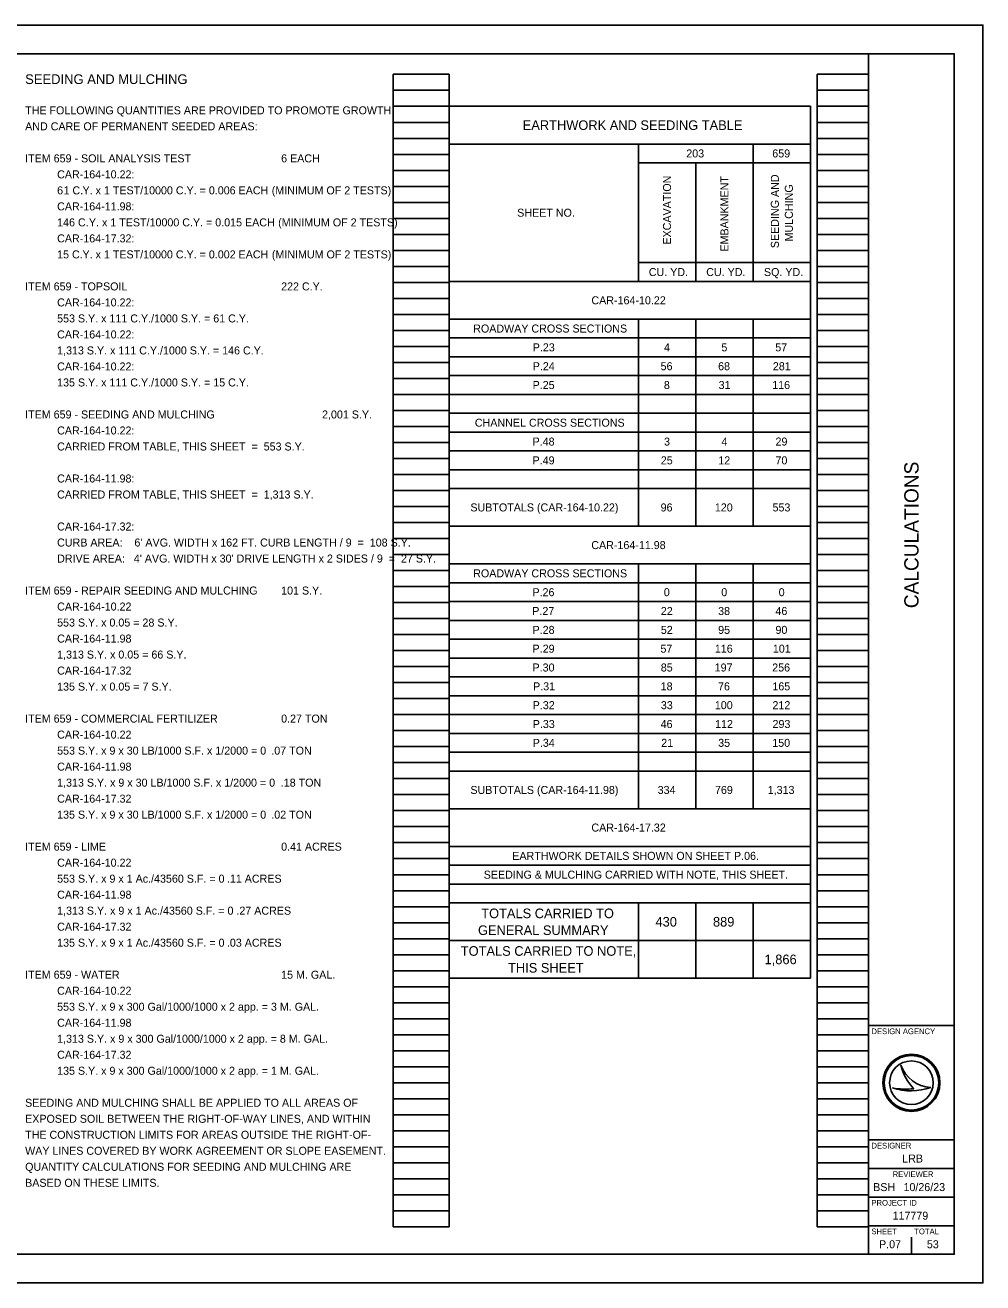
# Model space of a CAD drawing. Extents: x 0 to 34, y 0 to 22.
# Drawn here: x 17.24 to 34, y 0 to 22 of the extents above; entities that cross this region are included whole.
import ezdxf

# ---------------------------------------------------------------- set-up
doc = ezdxf.new("R2010")
doc.units = 0
for name, color, linetype in [('SH_Border', 7, 'Continuous'), ('SH_Cut_Line', 7, 'Continuous'), ('SH_Data', 7, 'Continuous'), ('SH_Text', 7, 'Continuous'), ('SV_X_Text', 7, 'Continuous')]:
    doc.layers.add(name, color=color, linetype=linetype)

msp = doc.modelspace()

# ---------------------------------------------------------------- linework, layer by layer
at = {"layer": 'SH_Border'}
for p, q in [((32, 0.5), (32, 21.5)), ((32, 4.5), (33.5, 4.5)), ((32, 2.5), (33.5, 2.5)), ((32, 2), (33.5, 2)), ((32, 1.5), (33.5, 1.5)), ((32, 1), (33.5, 1))]:
    msp.add_line(p, q, dxfattribs=at)
msp.add_lwpolyline([(1.5, 21.5), (33.5, 21.5), (33.5, 0.5), (1.5, 0.5)], close=True, dxfattribs=at)
at = {"layer": 'SH_Cut_Line'}
msp.add_lwpolyline([(0, 0), (34, 0), (34, 22), (0, 22)], close=True, dxfattribs=at)
at = {"layer": 'SH_Data'}
for p, q in [((23.68, 0.98), (23.68, 21.14)), ((23.68, 21.14), (24.66, 21.14)), ((24.66, 0.98), (24.66, 21.14)), ((31.1, 0.98), (31.1, 21.14)), ((31.1, 21.14), (32, 21.14)), ((32, 0.98), (32, 21.14)), ((23.68, 20.86), (24.66, 20.86)), ((31.1, 20.86), (32, 20.86)), ((23.68, 20.58), (24.66, 20.58)), ((31.1, 20.58), (32, 20.58)), ((23.68, 20.3), (24.66, 20.3)), ((31.1, 20.3), (32, 20.3)), ((23.68, 20.02), (24.66, 20.02)), ((31.1, 20.02), (32, 20.02)), ((23.68, 19.74), (24.66, 19.74)), ((31.1, 19.74), (32, 19.74)), ((23.68, 19.46), (24.66, 19.46)), ((31.1, 19.46), (32, 19.46)), ((23.68, 19.18), (24.66, 19.18)), ((31.1, 19.18), (32, 19.18)), ((23.68, 18.9), (24.66, 18.9)), ((31.1, 18.9), (32, 18.9)), ((23.68, 18.62), (24.66, 18.62)), ((31.1, 18.62), (32, 18.62)), ((23.68, 18.34), (24.66, 18.34)), ((31.1, 18.34), (32, 18.34)), ((23.68, 18.06), (24.66, 18.06)), ((31.1, 18.06), (32, 18.06)), ((23.68, 17.78), (24.66, 17.78)), ((31.1, 17.78), (32, 17.78)), ((23.68, 17.5), (24.66, 17.5)), ((31.1, 17.5), (32, 17.5)), ((23.68, 17.22), (24.66, 17.22)), ((31.1, 17.22), (32, 17.22)), ((23.68, 16.94), (24.66, 16.94)), ((31.1, 16.94), (32, 16.94)), ((23.68, 16.66), (24.66, 16.66)), ((31.1, 16.66), (32, 16.66)), ((23.68, 16.38), (24.66, 16.38)), ((31.1, 16.38), (32, 16.38)), ((23.68, 16.1), (24.66, 16.1)), ((31.1, 16.1), (32, 16.1)), ((23.68, 15.82), (24.66, 15.82)), ((31.1, 15.82), (32, 15.82)), ((23.68, 15.54), (24.66, 15.54)), ((31.1, 15.54), (32, 15.54)), ((23.68, 15.26), (24.66, 15.26)), ((31.1, 15.26), (32, 15.26)), ((23.68, 14.98), (24.66, 14.98)), ((31.1, 14.98), (32, 14.98)), ((23.68, 14.7), (24.66, 14.7)), ((31.1, 14.7), (32, 14.7)), ((23.68, 14.42), (24.66, 14.42)), ((31.1, 14.42), (32, 14.42)), ((23.68, 14.14), (24.66, 14.14)), ((31.1, 14.14), (32, 14.14)), ((23.68, 13.86), (24.66, 13.86)), ((31.1, 13.86), (32, 13.86)), ((23.68, 13.58), (24.66, 13.58)), ((31.1, 13.58), (32, 13.58)), ((23.68, 13.3), (24.66, 13.3)), ((31.1, 13.3), (32, 13.3)), ((23.68, 13.02), (24.66, 13.02)), ((31.1, 13.02), (32, 13.02)), ((23.68, 12.74), (24.66, 12.74)), ((31.1, 12.74), (32, 12.74)), ((23.68, 12.46), (24.66, 12.46)), ((31.1, 12.46), (32, 12.46)), ((23.68, 12.18), (24.66, 12.18)), ((31.1, 12.18), (32, 12.18)), ((23.68, 11.9), (24.66, 11.9)), ((31.1, 11.9), (32, 11.9)), ((23.68, 11.62), (24.66, 11.62)), ((31.1, 11.62), (32, 11.62)), ((23.68, 11.34), (24.66, 11.34)), ((31.1, 11.34), (32, 11.34)), ((23.68, 11.06), (24.66, 11.06)), ((31.1, 11.06), (32, 11.06)), ((23.68, 10.78), (24.66, 10.78)), ((31.1, 10.78), (32, 10.78)), ((23.68, 10.5), (24.66, 10.5)), ((31.1, 10.5), (32, 10.5)), ((23.68, 10.22), (24.66, 10.22)), ((31.1, 10.22), (32, 10.22)), ((23.68, 9.94), (24.66, 9.94)), ((31.1, 9.94), (32, 9.94)), ((23.68, 9.66), (24.66, 9.66)), ((31.1, 9.66), (32, 9.66)), ((23.68, 9.38), (24.66, 9.38)), ((31.1, 9.38), (32, 9.38)), ((23.68, 9.1), (24.66, 9.1)), ((31.1, 9.1), (32, 9.1)), ((23.68, 8.82), (24.66, 8.82)), ((31.1, 8.82), (32, 8.82)), ((23.68, 8.54), (24.66, 8.54)), ((31.1, 8.54), (32, 8.54)), ((23.68, 8.26), (24.66, 8.26)), ((31.1, 8.26), (32, 8.26)), ((23.68, 7.98), (24.66, 7.98)), ((31.1, 7.98), (32, 7.98)), ((23.68, 7.7), (24.66, 7.7)), ((31.1, 7.7), (32, 7.7)), ((23.68, 7.42), (24.66, 7.42)), ((31.1, 7.42), (32, 7.42)), ((23.68, 7.14), (24.66, 7.14)), ((31.1, 7.14), (32, 7.14)), ((23.68, 6.86), (24.66, 6.86)), ((31.1, 6.86), (32, 6.86)), ((23.68, 6.58), (24.66, 6.58)), ((31.1, 6.58), (32, 6.58)), ((23.68, 6.3), (24.66, 6.3)), ((31.1, 6.3), (32, 6.3)), ((23.68, 6.02), (24.66, 6.02)), ((31.1, 6.02), (32, 6.02)), ((23.68, 5.74), (24.66, 5.74)), ((31.1, 5.74), (32, 5.74)), ((23.68, 5.46), (24.66, 5.46)), ((31.1, 5.46), (32, 5.46)), ((23.68, 5.18), (24.66, 5.18)), ((31.1, 5.18), (32, 5.18)), ((23.68, 4.9), (24.66, 4.9)), ((31.1, 4.9), (32, 4.9)), ((23.68, 4.62), (24.66, 4.62)), ((31.1, 4.62), (32, 4.62)), ((23.68, 4.34), (24.66, 4.34)), ((31.1, 4.34), (32, 4.34)), ((23.68, 4.06), (24.66, 4.06)), ((31.1, 4.06), (32, 4.06)), ((23.68, 3.78), (24.66, 3.78)), ((31.1, 3.78), (32, 3.78)), ((32.567, 3.81), (32.567, 3.81)), ((23.68, 3.5), (24.66, 3.5)), ((31.1, 3.5), (32, 3.5)), ((32.417, 3.41), (32.417, 3.41)), ((32.75, 3.5), (32.75, 3.5)), ((33.087, 3.419), (33.087, 3.419)), ((23.68, 3.22), (24.66, 3.22)), ((31.1, 3.22), (32, 3.22)), ((23.68, 2.94), (24.66, 2.94)), ((31.1, 2.94), (32, 2.94)), ((23.68, 2.66), (24.66, 2.66)), ((31.1, 2.66), (32, 2.66)), ((23.68, 2.38), (24.66, 2.38)), ((31.1, 2.38), (32, 2.38)), ((23.68, 2.1), (24.66, 2.1)), ((31.1, 2.1), (32, 2.1)), ((23.68, 1.82), (24.66, 1.82)), ((31.1, 1.82), (32, 1.82)), ((23.68, 1.54), (24.66, 1.54)), ((31.1, 1.54), (32, 1.54)), ((23.68, 1.26), (24.66, 1.26)), ((31.1, 1.26), (32, 1.26)), ((23.68, 0.98), (24.66, 0.98)), ((31.1, 0.98), (32, 0.98)), ((32.375, 0.675), (32.375, 0.675)), ((32.75, 0.5), (32.75, 0.8))]:
    msp.add_line(p, q, dxfattribs=at)
for radius in [0.5, 0.477, 0.477, 0.382]:
    msp.add_circle((32.75, 3.5), radius, dxfattribs=at)
for centre, radius, start, end in [((33.116, 3.998), 0.58, 198.9257, 198.9319), ((33.347, 3.97), 0.796, 191.6379, 191.6421), ((33.116, 3.998), 0.58, 198.9319, 267.1657), ((33.347, 3.97), 0.796, 191.6421, 226.0947), ((32.739, 4.37), 1.013, 251.4576, 290.0832), ((32.648, 4.654), 1.266, 259.4964, 259.4995), ((32.739, 4.37), 1.013, 251.4527, 251.4576), ((32.648, 4.654), 1.266, 259.4995, 276.6672)]:
    msp.add_arc(centre, radius, start, end, dxfattribs=at)
at = {"layer": 'SH_Text'}
for p, q in [((24.66, 20.58), (30.985, 20.58)), ((24.66, 20.58), (24.66, 5.328)), ((30.985, 20.58), (30.985, 5.328)), ((24.66, 19.921), (30.985, 19.921)), ((27.971, 19.921), (27.971, 17.516)), ((29.98, 19.921), (29.98, 17.516)), ((27.971, 19.592), (30.985, 19.592)), ((28.975, 19.592), (28.975, 17.516)), ((27.971, 17.846), (30.985, 17.846)), ((24.66, 17.516), (30.985, 17.516)), ((24.66, 16.858), (30.985, 16.858)), ((27.971, 16.858), (27.971, 13.234)), ((28.975, 16.858), (28.975, 13.234)), ((29.98, 16.858), (29.98, 13.234)), ((24.66, 16.528), (30.985, 16.528)), ((24.66, 16.199), (30.985, 16.199)), ((24.66, 15.869), (30.985, 15.869)), ((24.66, 15.54), (30.985, 15.54)), ((24.66, 15.211), (30.985, 15.211)), ((24.66, 14.881), (30.985, 14.881)), ((24.66, 14.552), (30.985, 14.552)), ((24.66, 14.222), (30.985, 14.222)), ((24.66, 13.893), (30.985, 13.893)), ((24.66, 13.234), (30.985, 13.234)), ((24.66, 12.575), (30.985, 12.575)), ((27.971, 12.575), (27.971, 8.293)), ((28.975, 12.575), (28.975, 8.293)), ((29.98, 12.575), (29.98, 8.293)), ((24.66, 12.246), (30.985, 12.246)), ((24.66, 11.916), (30.985, 11.916)), ((24.66, 11.587), (30.985, 11.587)), ((24.66, 11.258), (30.985, 11.258)), ((24.66, 10.928), (30.985, 10.928)), ((24.66, 10.599), (30.985, 10.599)), ((24.66, 10.269), (30.985, 10.269)), ((24.66, 9.94), (30.985, 9.94)), ((24.66, 9.611), (30.985, 9.611)), ((24.66, 9.281), (30.985, 9.281)), ((24.66, 8.952), (30.985, 8.952)), ((24.66, 8.293), (30.985, 8.293)), ((24.66, 7.634), (30.985, 7.634)), ((24.66, 7.305), (30.985, 7.305)), ((24.66, 6.975), (30.985, 6.975)), ((24.66, 6.646), (30.985, 6.646)), ((27.971, 6.646), (27.971, 5.328)), ((28.975, 6.646), (28.975, 5.328)), ((29.98, 6.646), (29.98, 5.328)), ((24.66, 5.987), (30.985, 5.987)), ((24.66, 5.328), (30.985, 5.328))]:
    msp.add_line(p, q, dxfattribs=at)

# ---------------------------------------------------------------- texts
at = {"layer": 'SH_Data'}
for s, height, p in [('ITEM 659 - SOIL ANALYSIS TEST', 0.14, (17.24, 19.6)), ('6 EACH', 0.14, (21.72, 19.6)), ('CAR-164-10.22:', 0.14, (17.8, 19.32)), ('6', 0.14, (17.8, 19.04)), ('1 C.', 0.14, (17.912, 19.04)), ('Y. x 1 TEST/10000 C.Y. = 0.006 EACH ', 0.14, (18.244, 19.04)), (' (MINIMUM OF 2 TESTS)', 0.14, (21.504, 19.04)), ('CAR-164-11.98:', 0.14, (17.8, 18.76)), ('146 C.', 0.14, (17.8, 18.48)), ('Y. x 1 TEST/10000 C.Y. = 0.015 EACH ', 0.14, (18.356, 18.48)), (' (MINIMUM OF 2 TESTS)', 0.14, (21.616, 18.48)), ('CAR-164-17.32:', 0.14, (17.8, 18.2)), ('15 C.', 0.14, (17.8, 17.92)), ('Y. x 1 TEST/10000 C.Y. = 0.002 EACH', 0.14, (18.244, 17.92)), ('  (MINIMUM OF 2 TESTS)', 0.14, (21.454, 17.92)), ('ITEM 659 - TOPSOIL', 0.14, (17.24, 17.36)), ('222 C.Y.', 0.14, (21.72, 17.36)), ('CAR-164-10.22:', 0.14, (17.8, 17.08)), ('553 S.Y. x 111 C.Y./1000 S.Y. = 61 C.Y.', 0.14, (17.8, 16.8)), ('CAR-164-10.22:', 0.14, (17.8, 16.52)), ('1,313 S.Y. x 111 C.Y./1000 S.Y. = 146 C.Y.', 0.14, (17.8, 16.24)), ('CAR-164-10.22:', 0.14, (17.8, 15.96)), ('135 S.Y. x 111 C.Y./1000 S.Y. = 15 C.Y.', 0.14, (17.8, 15.68)), ('ITEM 659 - SEEDING AND MULCHING', 0.14, (17.24, 15.12)), ('   2,001 S.Y.', 0.14, (22.28, 15.12)), ('CAR-164-10.22:', 0.14, (17.8, 14.84)), ('CARRIED FROM TABLE, THIS SHEET  =  553 S.Y.', 0.14, (17.8, 14.56)), ('CAR-164-11.98:', 0.14, (17.8, 14)), ('CARRIED FROM TABLE, THIS SHEET  =  1,313 S.Y.', 0.14, (17.8, 13.72)), ('CAR-164-17.32:', 0.14, (17.8, 13.16)), ("CURB AREA:    6' AVG. WIDTH x 162 FT. CURB LENGTH / 9  =  108 S.Y.", 0.14, (17.8, 12.88)), ("DRIVE AREA:   4' AVG. WIDTH x 30' DRIVE LENGTH x 2 SIDES / 9  =  27 S.Y.", 0.14, (17.8, 12.6)), ('ITEM 659 - REPAIR SEEDING AND MULCHING', 0.14, (17.24, 12.04)), ('101 S.Y.', 0.14, (21.72, 12.04)), ('CAR-164-10.22', 0.14, (17.8, 11.76)), ('553 S.Y. x 0.05 = 28 S.Y.', 0.14, (17.8, 11.48)), ('CAR-164-11.98', 0.14, (17.8, 11.2)), ('1,313 S.Y. x 0.05 = 66 S.Y.', 0.14, (17.8, 10.92)), ('CAR-164-17.32', 0.14, (17.8, 10.64)), ('135 S.Y. x 0.05 = 7 S.Y.', 0.14, (17.8, 10.36)), ('ITEM 659 - COMMERCIAL FERTILIZER', 0.14, (17.24, 9.8)), ('0.27 TON', 0.14, (21.72, 9.8)), ('CAR-164-10.22', 0.14, (17.8, 9.52)), ('553 S.Y. x 9 x 30 LB/1000 S.F. x 1/2000 = 0', 0.14, (17.8, 9.24)), ('.07 TON', 0.14, (21.548, 9.24)), ('CAR-164-11.98', 0.14, (17.8, 8.96)), ('1,313 S.Y. x 9 x 30 LB/1000 S.F. x 1/2000 = 0', 0.14, (17.8, 8.68)), ('.18 TON', 0.14, (21.714, 8.68)), ('CAR-164-17.32', 0.14, (17.8, 8.4)), ('135 S.Y. x 9 x 30 LB/1000 S.F. x 1/2000 = 0', 0.14, (17.8, 8.12)), ('.02 TON', 0.14, (21.548, 8.12)), ('ITEM 659 - LIME', 0.14, (17.24, 7.56)), ('0.41 ACRES', 0.14, (21.72, 7.56)), ('CAR-164-10.22', 0.14, (17.8, 7.28)), ('553 S.Y. x 9 x 1 Ac./43560 S.F. = 0', 0.14, (17.8, 7)), ('.11 ACRES', 0.14, (20.771, 7)), ('CAR-164-11.98', 0.14, (17.8, 6.72)), ('1,313 S.Y. x 9 x 1 Ac./43560 S.F. = 0', 0.14, (17.8, 6.44)), ('.27 ACRES', 0.14, (20.937, 6.44)), ('CAR-164-17.32', 0.14, (17.8, 6.16)), ('135 S.Y. x 9 x 1 Ac./43560 S.F. = 0', 0.14, (17.8, 5.88)), ('.03 ACRES', 0.14, (20.771, 5.88)), ('ITEM 659 - WATER', 0.14, (17.24, 5.32)), ('15 M. GAL.', 0.14, (21.72, 5.32)), ('CAR-164-10.22', 0.14, (17.8, 5.04)), ('553 S.Y. x 9 x 300 Gal/1000/1000 x 2 app. = 3 M. GAL.', 0.14, (17.8, 4.76)), ('CAR-164-11.98', 0.14, (17.8, 4.48)), ('DESIGN AGENCY', 0.1, (32.05, 4.35)), ('1,313 S.Y. x 9 x 300 Gal/1000/1000 x 2 app. = 8 M. GAL.', 0.14, (17.8, 4.2)), ('CAR-164-17.32', 0.14, (17.8, 3.92)), ('135 S.Y. x 9 x 300 Gal/1000/1000 x 2 app. = 1 M. GAL.', 0.14, (17.8, 3.64)), ('DESIGNER', 0.1, (32.05, 2.35)), ('LRB', 0.14, (32.589, 2.105)), ('REVIEWER', 0.1, (32.422, 1.85)), ('BSH', 0.14, (32.08, 1.605)), ('10/26/23', 0.14, (32.611, 1.605)), ('PROJECT ID', 0.1, (32.05, 1.35)), ('117779', 0.14, (32.42, 1.105)), ('SHEET', 0.1, (32.05, 0.85)), ('TOTAL', 0.1, (32.8, 0.85)), ('P.07', 0.14, (32.183, 0.605)), ('53', 0.14, (33.02, 0.605))]:
    msp.add_text(s, height=height, dxfattribs=at).set_placement(p)
msp.add_text('CALCULATIONS', height=0.25, rotation=90, dxfattribs=at).set_placement((32.875, 11.801))
at = {"layer": 'SH_Text'}
for s, height, p in [('SEEDING AND MULCHING', 0.17, (17.24, 20.97)), ('EARTHWORK AND SEEDING TABLE', 0.168, (25.948, 20.167)), ('203', 0.14, (28.81, 19.686)), ('659', 0.14, (30.315, 19.686)), ('SHEET NO.', 0.14, (25.851, 18.649)), ('CU. YD.', 0.14, (28.154, 17.611)), ('CU. YD.', 0.14, (29.159, 17.611)), ('SQ. YD.', 0.14, (30.169, 17.611)), ('CAR-164-10.22', 0.14, (27.15, 17.117)), ('ROADWAY CROSS SECTIONS', 0.14, (25.081, 16.623)), ('P.23', 0.14, (26.123, 16.294)), ('4', 0.14, (28.421, 16.294)), ('5', 0.14, (29.424, 16.294)), ('57', 0.14, (30.367, 16.294)), ('P.24', 0.14, (26.123, 15.964)), ('56', 0.14, (28.361, 15.964)), ('68', 0.14, (29.367, 15.964)), ('281', 0.14, (30.325, 15.964)), ('P.25', 0.14, (26.121, 15.635)), ('8', 0.14, (28.418, 15.635)), ('31', 0.14, (29.376, 15.635)), ('116', 0.14, (30.314, 15.635)), ('CHANNEL CROSS SECTIONS', 0.14, (25.11, 14.976)), ('P.48', 0.14, (26.12, 14.646)), ('3', 0.14, (28.421, 14.646)), ('4', 0.14, (29.426, 14.646)), ('29', 0.14, (30.372, 14.646)), ('P.49', 0.14, (26.12, 14.317)), ('25', 0.14, (28.364, 14.317)), ('12', 0.14, (29.37, 14.317)), ('70', 0.14, (30.371, 14.317)), ('SUBTOTALS (CAR-164-10.22)', 0.14, (25.032, 13.494)), ('96', 0.14, (28.361, 13.494)), ('120', 0.14, (29.31, 13.494)), ('553', 0.14, (30.319, 13.494)), ('CAR-164-11.98', 0.14, (27.148, 12.835)), ('ROADWAY CROSS SECTIONS', 0.14, (25.081, 12.341)), ('P.26', 0.14, (26.118, 12.011)), ('0', 0.14, (28.417, 12.011)), ('0', 0.14, (29.422, 12.011)), ('0', 0.14, (30.427, 12.011)), ('P.27', 0.14, (26.115, 11.682)), ('22', 0.14, (28.365, 11.682)), ('38', 0.14, (29.367, 11.682)), ('46', 0.14, (30.37, 11.682)), ('P.28', 0.14, (26.12, 11.352)), ('52', 0.14, (28.365, 11.352)), ('95', 0.14, (29.368, 11.352)), ('90', 0.14, (30.371, 11.352)), ('P.29', 0.14, (26.12, 11.023)), ('57', 0.14, (28.358, 11.023)), ('116', 0.14, (29.31, 11.023)), ('101', 0.14, (30.325, 11.023)), ('P.30', 0.14, (26.119, 10.694)), ('85', 0.14, (28.364, 10.694)), ('197', 0.14, (29.307, 10.694)), ('256', 0.14, (30.314, 10.694)), ('P.31', 0.14, (26.129, 10.364)), ('18', 0.14, (28.362, 10.364)), ('76', 0.14, (29.366, 10.364)), ('165', 0.14, (30.317, 10.364)), ('P.32', 0.14, (26.122, 10.035)), ('33', 0.14, (28.365, 10.035)), ('100', 0.14, (29.31, 10.035)), ('212', 0.14, (30.318, 10.035)), ('P.33', 0.14, (26.123, 9.705)), ('46', 0.14, (28.361, 9.705)), ('112', 0.14, (29.314, 9.705)), ('293', 0.14, (30.319, 9.705)), ('P.34', 0.14, (26.123, 9.376)), ('21', 0.14, (28.371, 9.376)), ('35', 0.14, (29.368, 9.376)), ('150', 0.14, (30.315, 9.376)), ('SUBTOTALS (CAR-164-11.98)', 0.14, (25.032, 8.552)), ('334', 0.14, (28.309, 8.552)), ('769', 0.14, (29.312, 8.552)), ('1,313', 0.14, (30.235, 8.552)), ('CAR-164-17.32', 0.14, (27.15, 7.894)), ('EARTHWORK DETAILS SHOWN ON SHEET P.06.', 0.14, (25.765, 7.399)), ('SEEDING & MULCHING CARRIED WITH NOTE, THIS SHEET.', 0.14, (25.265, 7.07)), ('TOTALS CARRIED TO ', 0.168, (25.222, 6.379)), ('430', 0.168, (28.271, 6.232)), ('889', 0.168, (29.277, 6.232)), ('GENERAL SUMMARY', 0.168, (25.165, 6.085)), ('TOTALS CARRIED TO NOTE, ', 0.168, (24.864, 5.721)), ('1,866', 0.168, (30.18, 5.574)), ('THIS SHEET', 0.168, (25.691, 5.427)), ('SEEDING AND MULCHING SHALL BE APPLIED TO ALL AREAS OF ', 0.14, (17.24, 3.08)), ('EXPOSED SOIL BETWEEN THE RIGHT-OF-WAY LINES, AND WITHIN ', 0.14, (17.24, 2.8)), ('THE CONSTRUCTION LIMITS FOR AREAS OUTSIDE THE RIGHT-OF-', 0.14, (17.24, 2.52)), ('WAY LINES COVERED BY WORK AGREEMENT OR SLOPE EASEMENT. ', 0.14, (17.24, 2.24)), ('QUANTITY CALCULATIONS FOR SEEDING AND MULCHING ARE ', 0.14, (17.24, 1.96)), ('BASED ON THESE LIMITS.', 0.14, (17.24, 1.68))]:
    msp.add_text(s, height=height, dxfattribs=at).set_placement(p)
for s, p in [('SEEDING AND', (30.43, 18.099)), ('EXCAVATION', (28.543, 18.161)), ('EMBANKMENT', (29.548, 18.039)), ('MULCHING', (30.675, 18.217))]:
    msp.add_text(s, height=0.14, rotation=90, dxfattribs=at).set_placement(p)
at = {"layer": 'SV_X_Text'}
for s, p in [('THE FOLLOWING QUANTITIES ARE PROVIDED TO PROMOTE GROWTH ', (17.24, 20.44)), ('AND CARE OF PERMANENT SEEDED AREAS:', (17.24, 20.16))]:
    msp.add_text(s, height=0.14, dxfattribs=at).set_placement(p)

doc.saveas('drawing.dxf')
